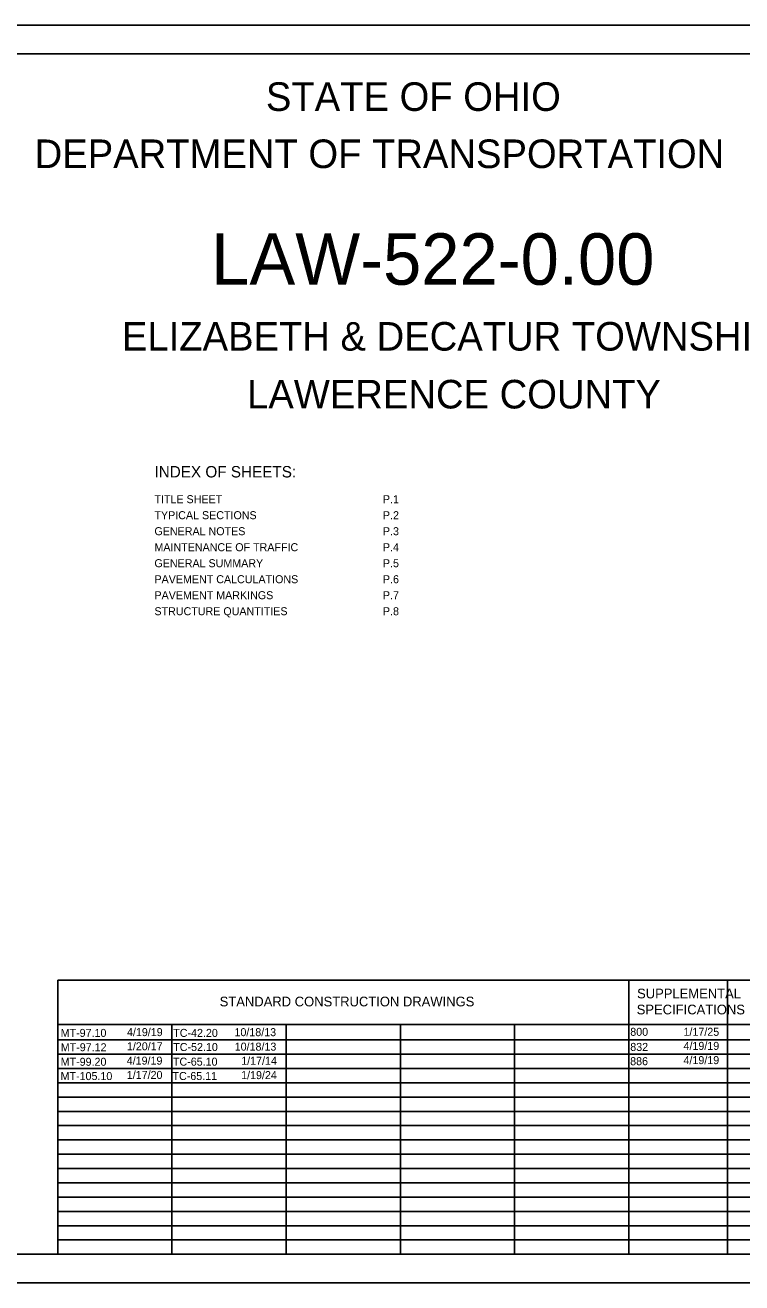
# Model space of a CAD drawing. Extents: x 0 to 82.7, y -0.2 to 22.
# Drawn here: x 9.58 to 22.13, y 0 to 22 of the extents above; entities that cross this region are included whole.
import ezdxf

# ---------------------------------------------------------------- set-up
doc = ezdxf.new("R2010")
doc.units = 0
for name, color, linetype in [('Default', 7, 'Continuous'), ('SH_Border', 7, 'Continuous'), ('SH_Cut_Line', 7, 'Continuous'), ('SH_Data', 7, 'Continuous'), ('SH_Text', 7, 'Continuous')]:
    doc.layers.add(name, color=color, linetype=linetype)

msp = doc.modelspace()

# ---------------------------------------------------------------- linework, layer by layer
at = {"layer": 'SH_Border'}
msp.add_lwpolyline([(1.5, 21.5), (33.5, 21.5), (33.5, 0.5), (1.5, 0.5)], close=True, dxfattribs=at)
at = {"layer": 'SH_Cut_Line'}
msp.add_lwpolyline([(0, 0), (34, 0), (34, 22), (0, 22)], close=True, dxfattribs=at)
at = {"layer": 'SH_Data'}
for p, q in [((10.15, 5.292), (23.6, 5.292)), ((10.15, 0.5), (10.15, 5.292)), ((20.15, 0.5), (20.15, 5.292)), ((21.875, 0.5), (21.875, 5.292)), ((10.15, 4.521), (23.6, 4.521)), ((12.15, 0.5), (12.15, 4.521)), ((14.15, 0.5), (14.15, 4.521)), ((16.15, 0.5), (16.15, 4.521)), ((18.15, 0.5), (18.15, 4.521)), ((10.15, 4.25), (23.6, 4.25)), ((10.15, 4), (23.6, 4)), ((10.15, 3.75), (23.6, 3.75)), ((10.15, 3.5), (23.6, 3.5)), ((10.15, 3.25), (23.6, 3.25)), ((10.15, 3), (23.6, 3)), ((10.15, 2.75), (23.6, 2.75)), ((10.15, 2.5), (23.6, 2.5)), ((10.15, 2.25), (23.6, 2.25)), ((10.15, 2), (23.6, 2)), ((10.15, 1.75), (23.6, 1.75)), ((10.15, 1.5), (23.6, 1.5)), ((10.15, 1.25), (23.6, 1.25)), ((10.15, 1), (23.6, 1)), ((10.15, 0.75), (23.6, 0.75))]:
    msp.add_line(p, q, dxfattribs=at)

# ---------------------------------------------------------------- texts
at = {"layer": 'Default'}
for s, height, p in [('LAW-522-0.00', 0.9, (12.837, 17.459)), ('ELIZABETH & DECATUR TOWNSHIPS', 0.5, (11.275, 16.307)), ('LAWERENCE COUNTY', 0.5, (13.466, 15.295)), ('P.1', 0.14, (15.844, 13.638)), ('P.2', 0.14, (15.844, 13.358)), ('P.3', 0.14, (15.844, 13.078)), ('P.4', 0.14, (15.844, 12.798)), ('P.5', 0.14, (15.844, 12.518)), ('P.6', 0.14, (15.844, 12.238)), ('P.7', 0.14, (15.844, 11.958)), ('P.8', 0.14, (15.844, 11.678)), ('MT-97.10', 0.14, (10.202, 4.302)), ('4/19/19', 0.14, (11.363, 4.316)), ('TC-42.20', 0.14, (12.173, 4.302)), ('10/18/13', 0.14, (13.245, 4.315)), ('800', 0.14, (20.174, 4.321)), ('1/17/25', 0.14, (21.106, 4.321)), ('MT-97.12', 0.14, (10.204, 4.051)), ('1/20/17', 0.14, (11.362, 4.068)), ('TC-52.10', 0.14, (12.173, 4.055)), ('10/18/13', 0.14, (13.249, 4.062)), ('832', 0.14, (20.174, 4.057)), ('4/19/19', 0.14, (21.106, 4.075)), ('4/19/19', 0.14, (11.359, 3.817)), ('1/17/14', 0.14, (13.363, 3.815)), ('4/19/19', 0.14, (21.106, 3.826)), ('MT-99.20', 0.14, (10.202, 3.797)), ('TC-65.10', 0.14, (12.168, 3.799)), ('886', 0.14, (20.172, 3.807)), ('MT-105.10', 0.14, (10.201, 3.547)), ('1/17/20', 0.14, (11.36, 3.567)), ('TC-65.11', 0.14, (12.16, 3.548)), ('1/19/24', 0.14, (13.362, 3.564))]:
    msp.add_text(s, height=height, dxfattribs=at).set_placement(p)
at = {"layer": 'SH_Text'}
for s, height, p in [('STATE OF OHIO', 0.5, (13.795, 20.5)), ('DEPARTMENT OF TRANSPORTATION', 0.5, (9.747, 19.5)), ('INDEX OF SHEETS:', 0.2, (11.844, 14.088)), ('TITLE SHEET', 0.14, (11.844, 13.638)), ('TYPICAL SECTIONS', 0.14, (11.844, 13.358)), ('GENERAL NOTES', 0.14, (11.844, 13.078)), ('MAINTENANCE OF TRAFFIC', 0.14, (11.844, 12.798)), ('GENERAL SUMMARY', 0.14, (11.844, 12.518)), ('PAVEMENT CALCULATIONS', 0.14, (11.844, 12.238)), ('PAVEMENT MARKINGS', 0.14, (11.844, 11.958)), ('STRUCTURE QUANTITIES', 0.14, (11.844, 11.678)), ('SUPPLEMENTAL', 0.17, (20.293, 4.976)), ('STANDARD CONSTRUCTION DRAWINGS', 0.17, (12.986, 4.836)), ('SPECIFICATIONS', 0.17, (20.287, 4.696))]:
    msp.add_text(s, height=height, dxfattribs=at).set_placement(p)

doc.saveas('drawing.dxf')
